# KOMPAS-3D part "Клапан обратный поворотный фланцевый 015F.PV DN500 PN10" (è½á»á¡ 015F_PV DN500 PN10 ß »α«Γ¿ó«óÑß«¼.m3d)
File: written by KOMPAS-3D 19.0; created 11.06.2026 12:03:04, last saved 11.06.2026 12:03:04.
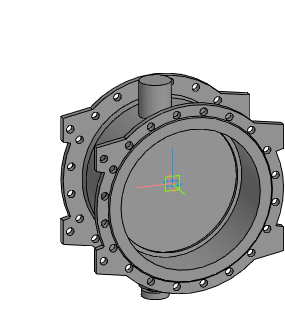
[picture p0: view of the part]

Document properties: Автор: Энергия; Полное имя файла: Z:\3.Личные\kachalov\001_3d для проектировщиков\5.5 Тип 015F.PV Клапан обратный поворотный с двумя эксцентриками\_stp_Клапан 015F.PV DN300-DN1200 с противовесом\Клапан 015F_PV DN500 PN10 с противовесом.m3d

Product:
- Part/product: Клапан обратный поворотный фланцевый 015F.PV DN500 PN10

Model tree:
1. Операция без истории:1
2. Сплайн:1
     Координата Y = 30; Координата Z = 250; Вес = 1; Координата X = 500; Координата Y = 95.8262; Координата Z = 250; Вес = 0.333333; Координата X = 500; Координата Y = 95.8262; Координата Z = -250; Вес = 0.333333; Координата Y = 30; Координата Z = -250; Вес = 1; Координата X = -500; Координата Y = -35.8262; Координата Z = -250; Вес = 0.333333; Координата X = -500; Координата Y = -35.8262; Координата Z = 250; Вес = 0.333333; Порядок = 4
